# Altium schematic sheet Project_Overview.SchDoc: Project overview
size A4; Date: Not used; ApprovedBy: Not used; CheckedBy: Not used; Author: Not used; CompanyName: STMicroelectronics; DrawnBy: Not used; Engineer: Not used; Organization: Not used; Address1: Not used; Address2: Not used; Address3: Not used; Address4: Not used; DocumentNumber: Not used; Revision: Not used; SheetNumber: 1; SheetTotal: 18
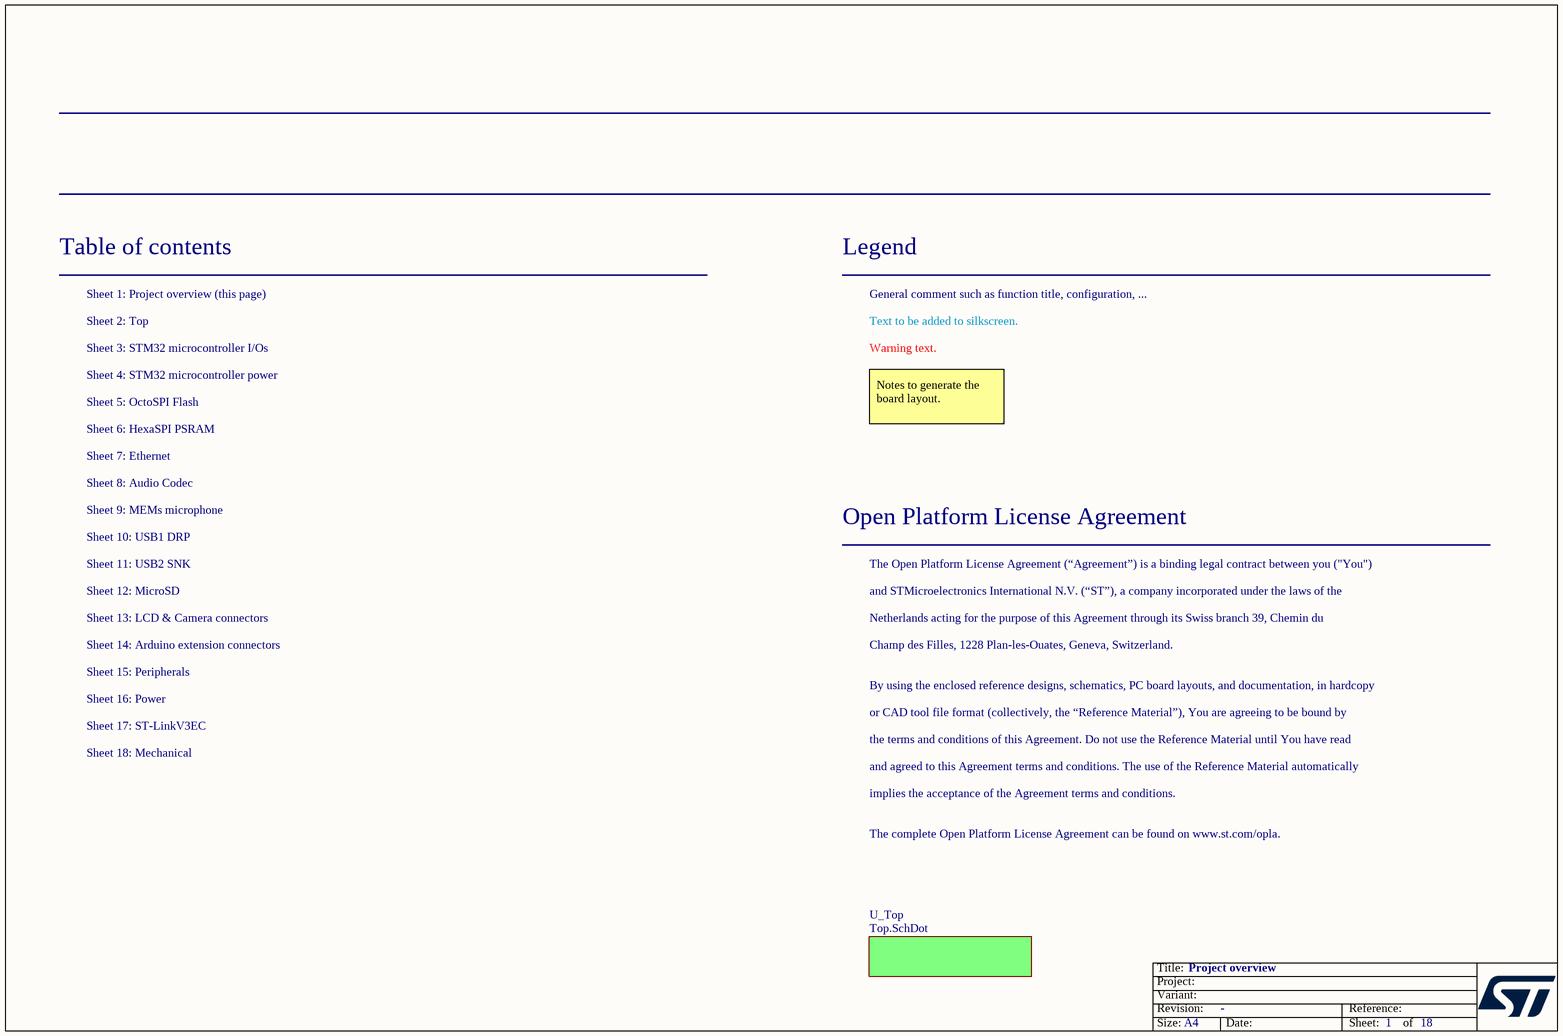
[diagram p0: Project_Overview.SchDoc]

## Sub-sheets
U_Top = Top.SchDot: no entries

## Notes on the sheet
- Table of contents
- Sheet 1: Project overview (this page)
- Legend
- General comment such as function title, configuration, ...
- Sheet 2: Top
- Sheet 3: STM32 microcontroller I/Os
- Sheet 4: STM32 microcontroller power
- Text to be added to silkscreen.
- Warning text.
- Sheet 5: OctoSPI Flash
- Sheet 6: HexaSPI PSRAM
- Notes to generate the board layout.
- Sheet 7: Ethernet
- Sheet 8: Audio Codec
- Sheet 9: MEMs microphone
- Sheet 10: USB1 DRP
- Sheet 11: USB2 SNK
- Open Platform License Agreement
- The Open Platform License Agreement (“Agreement”) is a binding legal contract between you ("You")
- Sheet 14: Arduino extension connectors
- Sheet 12: MicroSD
- Sheet 13: LCD & Camera connectors
- and STMicroelectronics International N.V. (“ST”), a company incorporated under the laws of the
- Netherlands acting for the purpose of this Agreement through its Swiss branch 39, Chemin du
- Champ des Filles, 1228 Plan-les-Ouates, Geneva, Switzerland.
- Sheet 16: Power
- Sheet 15: Peripherals
- By using the enclosed reference designs, schematics, PC board layouts, and documentation, in hardcopy
- or CAD tool file format (collectively, the “Reference Material”), You are agreeing to be bound by
- Sheet 17: ST-LinkV3EC
- Sheet 18: Mechanical
- the terms and conditions of this Agreement. Do not use the Reference Material until You have read
- and agreed to this Agreement terms and conditions. The use of the Reference Material automatically
- implies the acceptance of the Agreement terms and conditions.
- The complete Open Platform License Agreement can be found on www.st.com/opla.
